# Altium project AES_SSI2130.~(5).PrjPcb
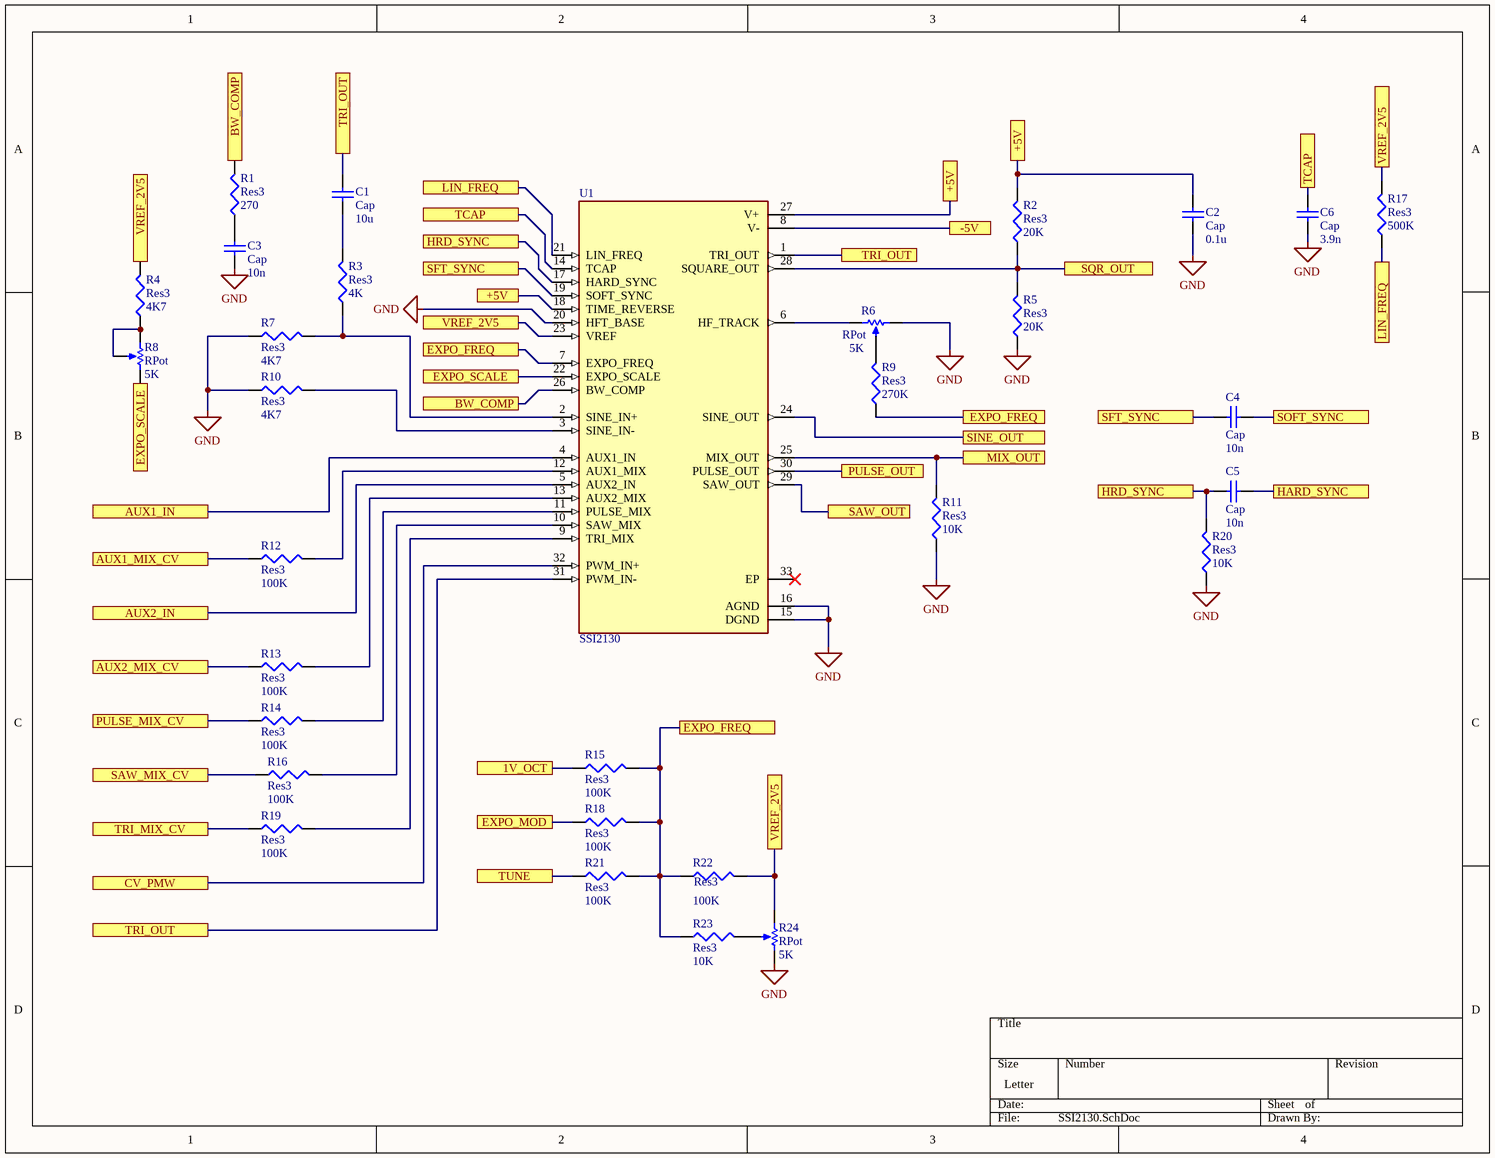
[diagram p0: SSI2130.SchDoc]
3 sheets, 67 parts. Net scope: flat (ports and power ports of the same name join across sheets).
Sheets:
  SSI2130.SchDoc
  power.SchDoc
  io.SchDoc

## Sheet SSI2130.SchDoc
size Letter

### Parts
C1  Cap  value 10u  [RAD-0.3]
C2  Cap  value 0.1u  [RAD-0.3]
C3  Cap  value 10n  [RAD-0.3]
C4  Cap  value 10n  [RAD-0.3]
C5  Cap  value 10n  [RAD-0.3]
C6  Cap  value 3.9n  [RAD-0.3]
R1  Res3  value 270  [J1-0603]
R2  Res3  value 20K  [J1-0603]
R3  Res3  value 4K  [J1-0603]
R4  Res3  value 4K7  [J1-0603]
R5  Res3  value 20K  [J1-0603]
R6  RPot  value 5K  [VR5]
R7  Res3  value 4K7  [J1-0603]
R8  RPot  value 5K  [VR5]
R9  Res3  value 270K  [J1-0603]
R10  Res3  value 4K7  [J1-0603]
R11  Res3  value 10K  [J1-0603]
R12  Res3  value 100K  [J1-0603]
R13  Res3  value 100K  [J1-0603]
R14  Res3  value 100K  [J1-0603]
R15  Res3  value 100K  [J1-0603]
R16  Res3  value 100K  [J1-0603]
R17  Res3  value 500K  [J1-0603]
R18  Res3  value 100K  [J1-0603]
R19  Res3  value 100K  [J1-0603]
R20  Res3  value 10K  [J1-0603]
R21  Res3  value 100K  [J1-0603]
R22  Res3  value 100K  [J1-0603]
R23  Res3  value 10K  [J1-0603]
R24  RPot  value 5K  [VR5]
U1  SSI2130  [QFN40P400X400X90-33N]

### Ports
1V_OCT, +5V, -5V, AUX1_IN, AUX1_MIX_CV, AUX2_IN, AUX2_MIX_CV, BW_COMP, CV_PMW, EXPO_FREQ, EXPO_MOD, EXPO_SCALE, HARD_SYNC, HRD_SYNC, LIN_FREQ, MIX_OUT, PULSE_MIX_CV, PULSE_OUT, SAW_MIX_CV, SAW_OUT, SFT_SYNC, SINE_OUT, SOFT_SYNC, SQR_OUT, TCAP, TRI_MIX_CV, TRI_OUT, TUNE, VREF_2V5

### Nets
GND: C2.1 C3.1 C6.1 R5.1 R6.2(BOT) R7.1 R10.1 R11.1 R20.1 R24.2(BOT) U1.15(DGND) U1.16(AGND) U1.20(HFT_BASE)
NetC1_1: C1.1 R3.2
NetC1_2: C1.2 U1.1(TRI_OUT) U1.31(PWM_IN-) ; port TRI_OUT
NetC2_2: C2.2 R2.2 U1.18(TIME_REVERSE) U1.27(V+) ; port +5V
NetC3_2: C3.2 R1.1
NetC4_1: C4.1 U1.19(SOFT_SYNC) ; port SFT_SYNC
NetC4_2: C4.2 ; port SOFT_SYNC
NetC5_1: C5.1 R20.2 U1.17(HARD_SYNC) ; port HRD_SYNC
NetC5_2: C5.2 ; port HARD_SYNC
NetC6_2: C6.2 U1.14(TCAP) ; port TCAP
NetC7_2: U1.8(V-) ; port -5V
NetP1_3: R15.1 ; port 1V_OCT
NetP1_4: R18.1 ; port EXPO_MOD
NetP1_5: R21.1 ; port TUNE
NetP1_6: U1.4(AUX1_IN) ; port AUX1_IN
NetP1_7: U1.5(AUX2_IN) ; port AUX2_IN
NetP1_8: R12.1 ; port AUX1_MIX_CV
NetP1_9: R13.1 ; port AUX2_MIX_CV
NetP1_10: R14.1 ; port PULSE_MIX_CV
NetP1_11: R16.1 ; port SAW_MIX_CV
NetP1_12: R19.1 ; port TRI_MIX_CV
NetP2_7: U1.32(PWM_IN+) ; port CV_PMW
NetP2_10: R4.2 R17.2 R22.2 R24.1(TOP) U1.23(VREF) ; port VREF_2V5
NetR1_2: R1.2 U1.26(BW_COMP) ; port BW_COMP
NetR2_1: R2.1 R5.2 U1.28(SQUARE_OUT) ; port SQR_OUT
NetR3_1: R3.1 R7.2 U1.2(SINE_IN+)
NetR4_1: R4.1 R8.1(TOP) R8.3(TAP)
NetR6_1: R6.1(TOP) U1.6(HF_TRACK)
NetR6_3: R6.3(TAP) R9.2
NetR8_2: R8.2(BOT) U1.22(EXPO_SCALE) ; port EXPO_SCALE
NetR9_1: R9.1 R15.2 R18.2 R21.2 R22.1 R23.1 U1.7(EXPO_FREQ) ; port EXPO_FREQ
NetR10_2: R10.2 U1.3(SINE_IN-)
NetR11_2: R11.2 U1.25(MIX_OUT) ; port MIX_OUT
NetR12_2: R12.2 U1.12(AUX1_MIX)
NetR13_2: R13.2 U1.13(AUX2_MIX)
NetR14_2: R14.2 U1.11(PULSE_MIX)
NetR16_2: R16.2 U1.10(SAW_MIX)
NetR17_1: R17.1 U1.21(LIN_FREQ) ; port LIN_FREQ
NetR19_2: R19.2 U1.9(TRI_MIX)
NetR23_2: R23.2 R24.3(TAP)
NetR40_1: U1.30(PULSE_OUT) ; port PULSE_OUT
NetR44_1: U1.29(SAW_OUT) ; port SAW_OUT
NetU1_24: U1.24(SINE_OUT) ; port SINE_OUT

Not connected (* = marked no-connect by the designer): U1 33(EP)*

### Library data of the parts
C1-C6 = Cap: Capacitor
R1-R5 R7 R9-R23 = Res3: Resistor
R6 R8 R24 = RPot: Potentiometer; Sim Note: Enter the Resistance value and the set point into parameter fields.; Set Position: 0.5
U1 = SSI2130: Voltage controlled oscillator subsystem for high-performance electronic musical instruments; MF: Sound Semiconductor

## Sheet power.SchDoc
size Letter
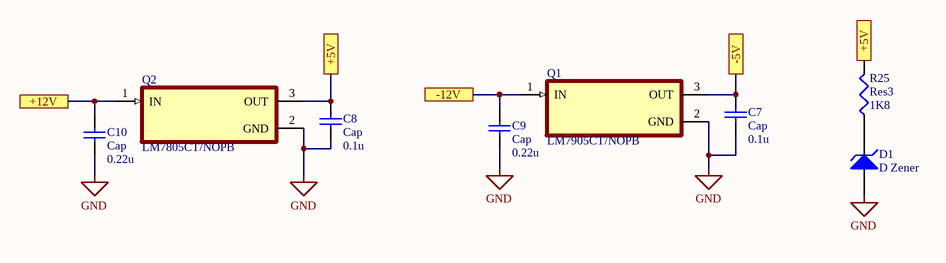
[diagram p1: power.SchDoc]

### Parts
C7  Cap  value 0.1u  [RAD-0.3]
C8  Cap  value 0.1u  [RAD-0.3]
C9  Cap  value 0.22u  [RAD-0.3]
C10  Cap  value 0.22u  [RAD-0.3]
D1  D Zener  [DIODE-0.7]
Q1  LM7905CT/NOPB  [TO254P1054X470X1955-3]
Q2  LM7805CT/NOPB  [TO254P1054X470X1955-3]
R25  Res3  value 1K8  [J1-0603]

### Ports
+5V, +12V, -5V, -12V

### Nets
GND: C7.1 C8.1 C9.1 C10.1 D1.1(A) Q1.2(GND) Q2.2(GND)
NetC2_2: C8.2 Q2.3(OUT) R25.2 ; port +5V
NetC7_2: C7.2 Q1.3(OUT) ; port -5V
NetC9_2: C9.2 Q1.1(IN) ; port -12V
NetC10_2: C10.2 Q2.1(IN) ; port +12V
NetD1_2: D1.2(K) R25.1

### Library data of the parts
C7-C10 = Cap: Capacitor
D1 = D Zener: Zener Diode
Q1 Q2 = LM7805CT/NOPB: 1.5-A, 30-V, linear voltage regulator 3-TO-220 0 to 125; MF: Texas Instruments
R25 = Res3: Resistor

## Sheet io.SchDoc
size Letter
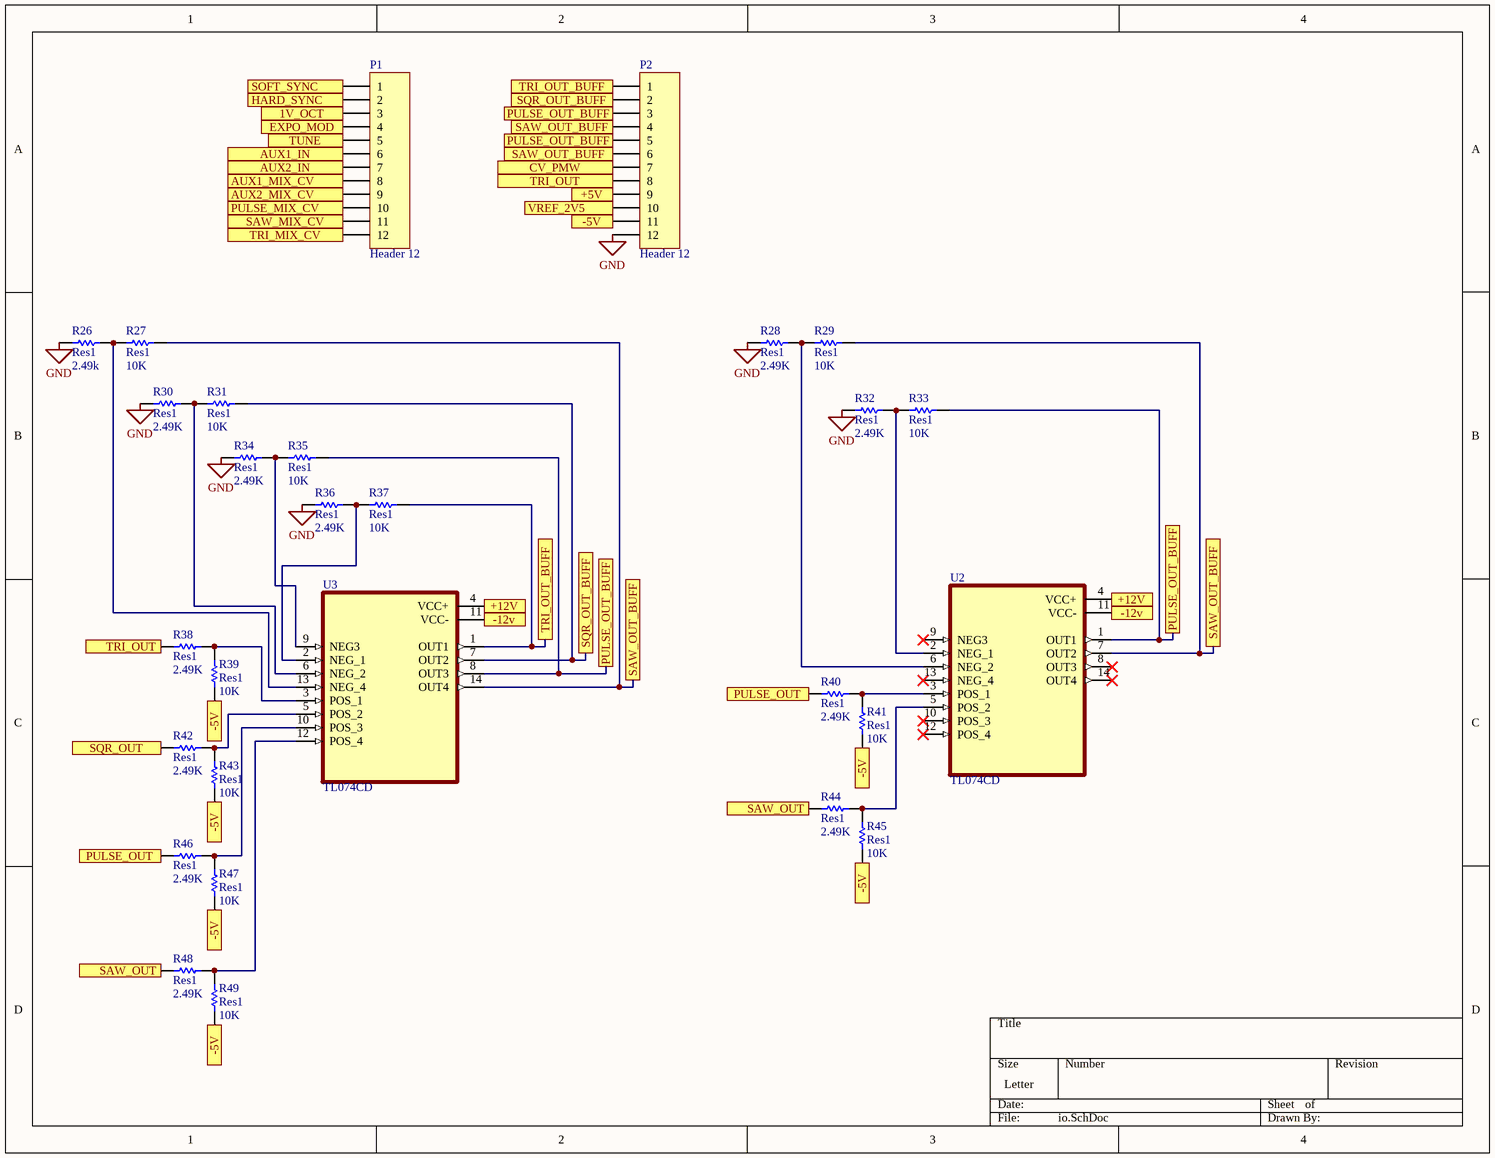
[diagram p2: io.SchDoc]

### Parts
P1  Header 12  [HDR1X12]
P2  Header 12  [HDR1X12]
R26  Res1  value 2.49k  [AXIAL-0.3]
R27  Res1  value 10K  [AXIAL-0.3]
R28  Res1  value 2.49K  [AXIAL-0.3]
R29  Res1  value 10K  [AXIAL-0.3]
R30  Res1  value 2.49K  [AXIAL-0.3]
R31  Res1  value 10K  [AXIAL-0.3]
R32  Res1  value 2.49K  [AXIAL-0.3]
R33  Res1  value 10K  [AXIAL-0.3]
R34  Res1  value 2.49K  [AXIAL-0.3]
R35  Res1  value 10K  [AXIAL-0.3]
R36  Res1  value 2.49K  [AXIAL-0.3]
R37  Res1  value 10K  [AXIAL-0.3]
R38  Res1  value 2.49K  [AXIAL-0.3]
R39  Res1  value 10K  [AXIAL-0.3]
R40  Res1  value 2.49K  [AXIAL-0.3]
R41  Res1  value 10K  [AXIAL-0.3]
R42  Res1  value 2.49K  [AXIAL-0.3]
R43  Res1  value 10K  [AXIAL-0.3]
R44  Res1  value 2.49K  [AXIAL-0.3]
R45  Res1  value 10K  [AXIAL-0.3]
R46  Res1  value 2.49K  [AXIAL-0.3]
R47  Res1  value 10K  [AXIAL-0.3]
R48  Res1  value 2.49K  [AXIAL-0.3]
R49  Res1  value 10K  [AXIAL-0.3]
U2  TL074CD  [SOIC127P600X175-14N]
U3  TL074CD  [SOIC127P600X175-14N]

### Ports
1V_OCT, +5V, +12V, -5V, -12v, AUX1_IN, AUX1_MIX_CV, AUX2_IN, AUX2_MIX_CV, CV_PMW, EXPO_MOD, HARD_SYNC, PULSE_MIX_CV, PULSE_OUT, PULSE_OUT_BUFF, SAW_MIX_CV, SAW_OUT, SAW_OUT_BUFF, SOFT_SYNC, SQR_OUT, SQR_OUT_BUFF, TRI_MIX_CV, TRI_OUT, TRI_OUT_BUFF, TUNE, VREF_2V5

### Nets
GND: P2.12 R26.1 R28.1 R30.1 R32.1 R34.1 R36.1
NetC1_2: P2.8 R38.1 ; port TRI_OUT
NetC2_2: P2.9 ; port +5V
NetC4_2: P1.1 ; port SOFT_SYNC
NetC5_2: P1.2 ; port HARD_SYNC
NetC7_2: P2.11 R39.1 R41.1 R43.1 R45.1 R47.1 R49.1 ; port -5V
NetC9_2: U2.11(VCC-) U3.11(VCC-) ; port -12v
NetC10_2: U2.4(VCC+) U3.4(VCC+) ; port +12V
NetP1_3: P1.3 ; port 1V_OCT
NetP1_4: P1.4 ; port EXPO_MOD
NetP1_5: P1.5 ; port TUNE
NetP1_6: P1.6 ; port AUX1_IN
NetP1_7: P1.7 ; port AUX2_IN
NetP1_8: P1.8 ; port AUX1_MIX_CV
NetP1_9: P1.9 ; port AUX2_MIX_CV
NetP1_10: P1.10 ; port PULSE_MIX_CV
NetP1_11: P1.11 ; port SAW_MIX_CV
NetP1_12: P1.12 ; port TRI_MIX_CV
NetP2_1: P2.1 R37.2 U3.1(OUT1) ; port TRI_OUT_BUFF
NetP2_2: P2.2 R31.2 U3.7(OUT2) ; port SQR_OUT_BUFF
NetP2_3: P2.3 P2.5 R33.2 R35.2 U2.1(OUT1) U3.8(OUT3) ; port PULSE_OUT_BUFF
NetP2_4: P2.4 P2.6 R27.2 R29.2 U2.7(OUT2) U3.14(OUT4) ; port SAW_OUT_BUFF
NetP2_7: P2.7 ; port CV_PMW
NetP2_10: P2.10 ; port VREF_2V5
NetR2_1: R42.1 ; port SQR_OUT
NetR26_2: R26.2 R27.1 U3.13(NEG_4)
NetR28_2: R28.2 R29.1 U2.6(NEG_2)
NetR30_2: R30.2 R31.1 U3.6(NEG_2)
NetR32_2: R32.2 R33.1 U2.2(NEG_1)
NetR34_2: R34.2 R35.1 U3.9(NEG3)
NetR36_2: R36.2 R37.1 U3.2(NEG_1)
NetR38_2: R38.2 R39.2 U3.3(POS_1)
NetR40_1: R40.1 R46.1 ; port PULSE_OUT
NetR40_2: R40.2 R41.2 U2.3(POS_1)
NetR42_2: R42.2 R43.2 U3.5(POS_2)
NetR44_1: R44.1 R48.1 ; port SAW_OUT
NetR44_2: R44.2 R45.2 U2.5(POS_2)
NetR46_2: R46.2 R47.2 U3.10(POS_3)
NetR48_2: R48.2 R49.2 U3.12(POS_4)

Not connected (* = marked no-connect by the designer): U2 8(OUT3)* 9(NEG3)* 10(POS_3)* 12(POS_4)* 13(NEG_4)* 14(OUT4)*

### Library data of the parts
P1 P2 = Header 12: Header, 12-Pin
R26-R49 = Res1: Resistor
U2 U3 = TL074CD: Quad Low-Noise JFET-Input General-Purpose Operational Amplifier 14-SOIC 0 to 70; MF: Texas Instruments

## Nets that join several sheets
GND: SSI2130 (13 pins), power (7 pins), io (7 pins)
NetC1_2: SSI2130 (C1.2 U1.1 U1.31), io (P2.8 R38.1)
NetC2_2: SSI2130 (C2.2 R2.2 U1.18 U1.27), power (C8.2 Q2.3 R25.2), io (P2.9)
NetC4_2: SSI2130 (C4.2), io (P1.1)
NetC5_2: SSI2130 (C5.2), io (P1.2)
NetC7_2: SSI2130 (U1.8), power (C7.2 Q1.3), io (7 pins)
NetC9_2: power (C9.2 Q1.1), io (U2.11 U3.11)
NetC10_2: power (C10.2 Q2.1), io (U2.4 U3.4)
NetP1_3: SSI2130 (R15.1), io (P1.3)
NetP1_4: SSI2130 (R18.1), io (P1.4)
NetP1_5: SSI2130 (R21.1), io (P1.5)
NetP1_6: SSI2130 (U1.4), io (P1.6)
NetP1_7: SSI2130 (U1.5), io (P1.7)
NetP1_8: SSI2130 (R12.1), io (P1.8)
NetP1_9: SSI2130 (R13.1), io (P1.9)
NetP1_10: SSI2130 (R14.1), io (P1.10)
NetP1_11: SSI2130 (R16.1), io (P1.11)
NetP1_12: SSI2130 (R19.1), io (P1.12)
NetP2_7: SSI2130 (U1.32), io (P2.7)
NetP2_10: SSI2130 (5 pins), io (P2.10)
NetR2_1: SSI2130 (R2.1 R5.2 U1.28), io (R42.1)
NetR40_1: SSI2130 (U1.30), io (R40.1 R46.1)
NetR44_1: SSI2130 (U1.29), io (R44.1 R48.1)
